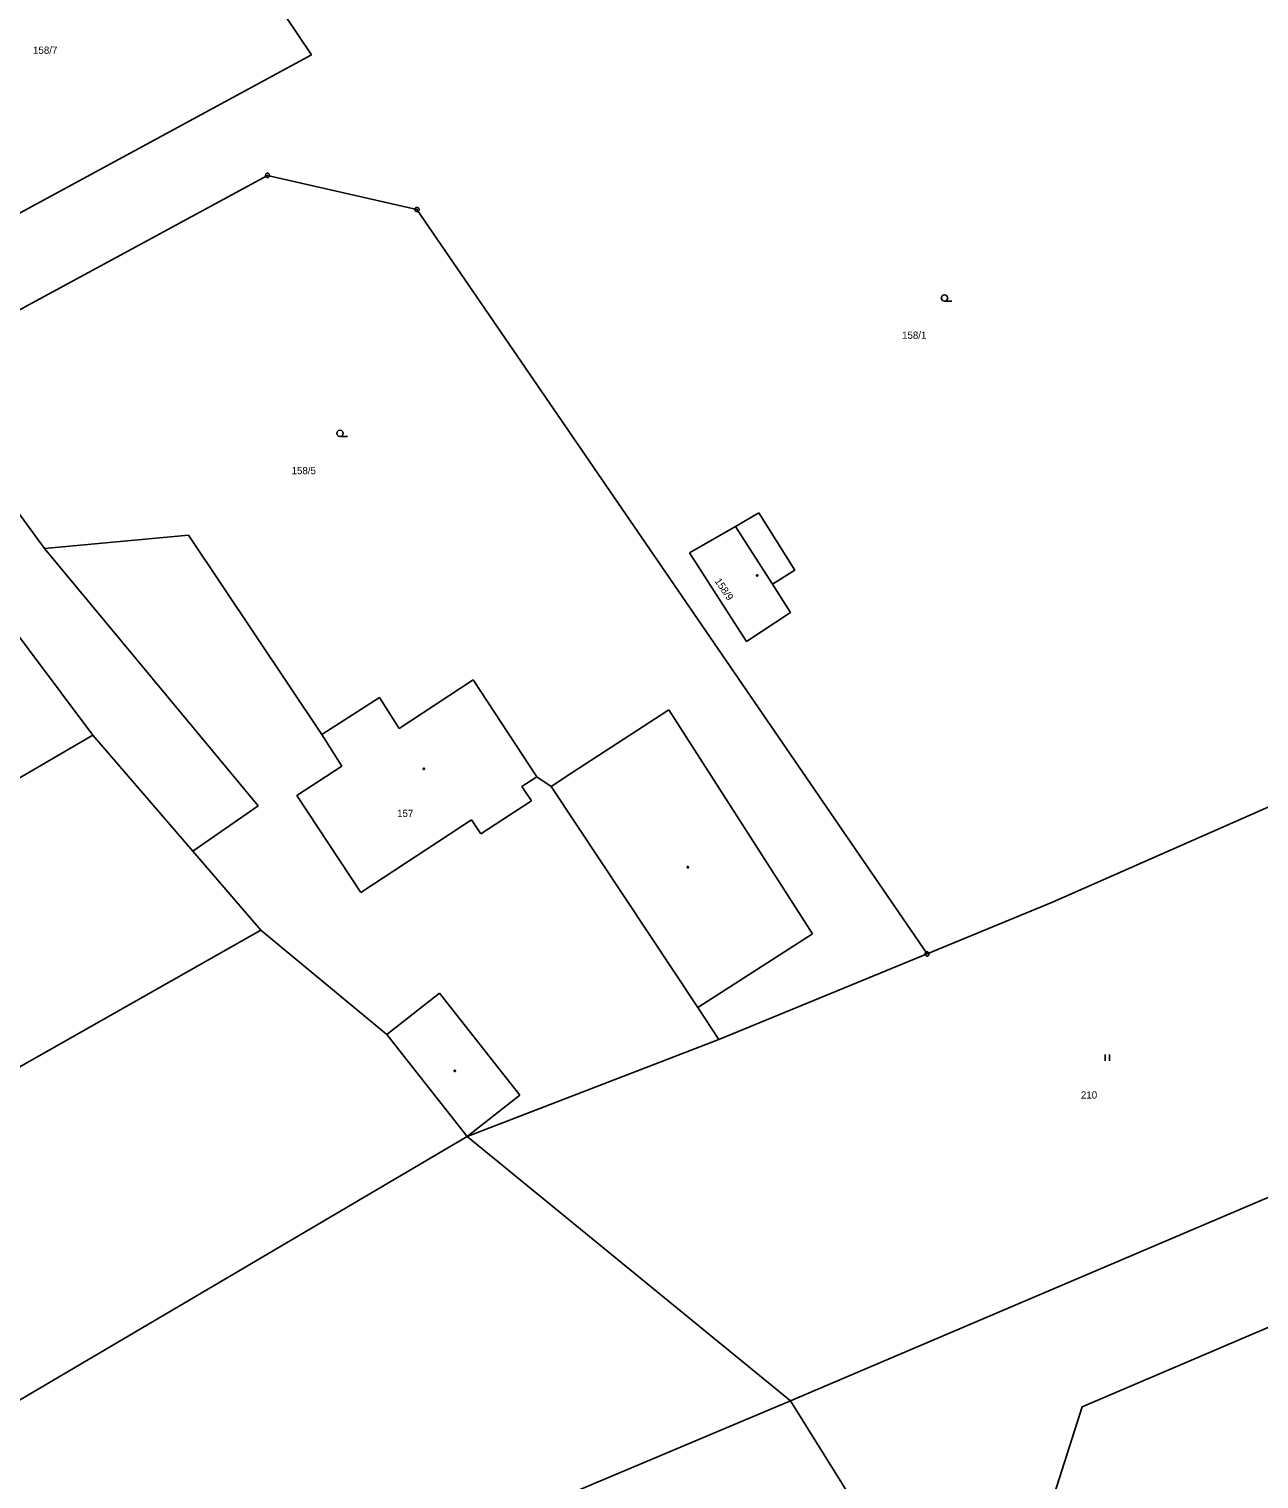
# Model space of a CAD drawing. Extents: x -871430 to -870620, y -1010094 to -1009649.
# Drawn here: x -870895.2 to -870823.3, y -1009941.8 to -1009857 of the extents above; entities that cross this region are included whole.
import ezdxf

# ---------------------------------------------------------------- set-up
doc = ezdxf.new("R2010")
doc.units = 0
for name, color, linetype in [('Vrstva 1', 7, 'Continuous'), ('Vrstva 2', 7, 'Continuous'), ('Vrstva 3', 7, 'Continuous'), ('Vrstva 4', 7, 'Continuous'), ('Vrstva 5', 7, 'Continuous'), ('Vrstva 8', 7, 'Continuous')]:
    doc.layers.add(name, color=color, linetype=linetype)

msp = doc.modelspace()

# ---------------------------------------------------------------- linework, layer by layer
at = {"layer": 'Vrstva 1'}
for p, q in [((-870878.69, -1009858.54), (-870885.13, -1009848.9)), ((-870878.69, -1009858.54), (-870899.31, -1009869.72)), ((-870902.04, -1009876.85), (-870881.26, -1009865.58)), ((-870881.26, -1009865.58), (-870872.52, -1009867.58)), ((-870872.52, -1009867.58), (-870842.69, -1009911.12)), ((-870902.04, -1009876.85), (-870894.31, -1009887.4)), ((-870853.89, -1009886.11), (-870852.53, -1009885.32)), ((-870852.53, -1009885.32), (-870850.42, -1009888.67)), ((-870856.59, -1009887.66), (-870853.89, -1009886.11)), ((-870891.48, -1009898.32), (-870899.84, -1009887.16)), ((-870894.31, -1009887.4), (-870885.88, -1009886.62)), ((-870885.88, -1009886.62), (-870878.09, -1009898.28)), ((-870881.8, -1009902.45), (-870894.31, -1009887.4)), ((-870853.25, -1009892.85), (-870856.59, -1009887.66)), ((-870850.42, -1009888.67), (-870851.73, -1009889.5)), ((-870851.73, -1009889.5), (-870850.68, -1009891.15)), ((-870850.68, -1009891.15), (-870853.25, -1009892.85)), ((-870835.36, -1009908.1), (-870803.69, -1009894.13)), ((-870873.56, -1009897.93), (-870869.24, -1009895.09)), ((-870865.51, -1009900.76), (-870869.24, -1009895.09)), ((-870878.09, -1009898.28), (-870874.71, -1009896.12)), ((-870873.56, -1009897.93), (-870874.71, -1009896.12)), ((-870863.46, -1009900.53), (-870857.8, -1009896.85)), ((-870857.8, -1009896.85), (-870849.39, -1009909.94)), ((-870937.35, -1009925.05), (-870891.48, -1009898.32)), ((-870885.63, -1009905.11), (-870891.48, -1009898.32)), ((-870864.68, -1009901.32), (-870865.51, -1009900.76)), ((-870864.68, -1009901.32), (-870863.46, -1009900.53)), ((-870885.63, -1009905.11), (-870881.8, -1009902.45)), ((-870881.66, -1009909.72), (-870885.63, -1009905.11)), ((-870842.69, -1009911.12), (-870835.36, -1009908.1)), ((-870935.49, -1009940.26), (-870881.66, -1009909.72)), ((-870874.28, -1009915.83), (-870881.66, -1009909.72)), ((-870856.1, -1009914.25), (-870849.39, -1009909.94)), ((-870842.69, -1009911.12), (-870854.86, -1009916.13)), ((-870854.86, -1009916.13), (-870856.1, -1009914.25)), ((-870850.67, -1009937.26), (-870796.84, -1009914.3)), ((-870869.59, -1009921.79), (-870874.28, -1009915.83)), ((-870854.86, -1009916.13), (-870869.59, -1009921.79)), ((-870924.06, -1009953.89), (-870869.59, -1009921.79)), ((-870850.67, -1009937.26), (-870869.59, -1009921.79)), ((-870850.67, -1009937.26), (-870890.37, -1009953.94)), ((-870837.15, -1009958.98), (-870850.67, -1009937.26))]:
    msp.add_line(p, q, dxfattribs=at)
msp.add_lwpolyline([(-870830.66, -1009955.85), (-870836.43, -1009946.41), (-870833.62, -1009937.6), (-870794.48, -1009920.9)], dxfattribs=at)
at = {"layer": 'Vrstva 3'}
for p, q in [((-870832.265, -1009917.005), (-870832.265, -1009917.38)), ((-870832.015, -1009917.38), (-870832.015, -1009917.005))]:
    msp.add_line(p, q, dxfattribs=at)
for points in [[(-870841.67, -1009872.94), (-870841.765, -1009872.915), (-870841.832, -1009872.845), (-870841.858, -1009872.752), (-870841.832, -1009872.66), (-870841.765, -1009872.59), (-870841.67, -1009872.565), (-870841.575, -1009872.59), (-870841.508, -1009872.66), (-870841.482, -1009872.752), (-870841.508, -1009872.845), (-870841.575, -1009872.915), (-870841.67, -1009872.94), (-870841.232, -1009872.94)], [(-870877.02, -1009880.86), (-870877.115, -1009880.835), (-870877.182, -1009880.765), (-870877.208, -1009880.672), (-870877.182, -1009880.58), (-870877.115, -1009880.51), (-870877.02, -1009880.485), (-870876.925, -1009880.51), (-870876.858, -1009880.58), (-870876.832, -1009880.672), (-870876.858, -1009880.765), (-870876.925, -1009880.835), (-870877.02, -1009880.86), (-870876.582, -1009880.86)]]:
    msp.add_lwpolyline(points, dxfattribs=at)
at = {"layer": 'Vrstva 4'}
for p, q in [((-870851.73, -1009889.5), (-870853.89, -1009886.11)), ((-870876.91, -1009900.13), (-870878.09, -1009898.28)), ((-870879.54, -1009901.86), (-870876.91, -1009900.13)), ((-870865.51, -1009900.76), (-870866.38, -1009901.33)), ((-870865.83, -1009902.16), (-870866.38, -1009901.33)), ((-870864.68, -1009901.32), (-870856.1, -1009914.25)), ((-870875.81, -1009907.53), (-870879.54, -1009901.86)), ((-870865.83, -1009902.16), (-870868.79, -1009904.1)), ((-870869.33, -1009903.27), (-870875.81, -1009907.53)), ((-870868.79, -1009904.1), (-870869.33, -1009903.27)), ((-870871.2, -1009913.41), (-870874.28, -1009915.83)), ((-870871.2, -1009913.41), (-870866.51, -1009919.37)), ((-870869.59, -1009921.79), (-870866.51, -1009919.37))]:
    msp.add_line(p, q, dxfattribs=at)
at = {"layer": 'Vrstva 5'}
for points in [[(-870852.62, -1009888.938), (-870852.595, -1009888.942), (-870852.582, -1009888.965), (-870852.578, -1009888.98), (-870852.582, -1009889.002), (-870852.602, -1009889.02), (-870852.62, -1009889.022), (-870852.642, -1009889.015), (-870852.658, -1009889), (-870852.662, -1009888.98), (-870852.658, -1009888.958), (-870852.638, -1009888.94), (-870852.62, -1009888.938)], [(-870872.12, -1009900.248), (-870872.095, -1009900.253), (-870872.082, -1009900.275), (-870872.078, -1009900.29), (-870872.082, -1009900.312), (-870872.102, -1009900.33), (-870872.12, -1009900.332), (-870872.142, -1009900.325), (-870872.158, -1009900.31), (-870872.162, -1009900.29), (-870872.158, -1009900.268), (-870872.138, -1009900.25), (-870872.12, -1009900.248)], [(-870856.658, -1009906.003), (-870856.635, -1009906.04), (-870856.658, -1009906.078), (-870856.702, -1009906.078), (-870856.725, -1009906.04), (-870856.702, -1009906.003), (-870856.658, -1009906.003)], [(-870870.288, -1009917.922), (-870870.265, -1009917.96), (-870870.288, -1009917.997), (-870870.332, -1009917.997), (-870870.355, -1009917.96), (-870870.332, -1009917.922), (-870870.288, -1009917.922)]]:
    msp.add_lwpolyline(points, dxfattribs=at)
at = {"layer": 'Vrstva 8'}
for p, q in [((-870881.272, -1009865.58), (-870881.248, -1009865.58)), ((-870872.532, -1009867.58), (-870872.508, -1009867.58)), ((-870842.702, -1009911.12), (-870842.678, -1009911.12))]:
    msp.add_line(p, q, dxfattribs=at)
for points in [[(-870881.222, -1009865.46), (-870881.16, -1009865.508), (-870881.135, -1009865.58), (-870881.16, -1009865.652), (-870881.222, -1009865.7), (-870881.298, -1009865.7), (-870881.36, -1009865.652), (-870881.385, -1009865.58), (-870881.36, -1009865.508), (-870881.298, -1009865.46), (-870881.222, -1009865.46)], [(-870872.482, -1009867.46), (-870872.42, -1009867.508), (-870872.395, -1009867.58), (-870872.42, -1009867.652), (-870872.482, -1009867.7), (-870872.558, -1009867.7), (-870872.62, -1009867.652), (-870872.645, -1009867.58), (-870872.62, -1009867.508), (-870872.558, -1009867.46), (-870872.482, -1009867.46)], [(-870842.652, -1009911), (-870842.59, -1009911.048), (-870842.565, -1009911.12), (-870842.59, -1009911.192), (-870842.652, -1009911.24), (-870842.727, -1009911.24), (-870842.79, -1009911.192), (-870842.815, -1009911.12), (-870842.79, -1009911.048), (-870842.727, -1009911), (-870842.652, -1009911)]]:
    msp.add_lwpolyline(points, dxfattribs=at)

# ---------------------------------------------------------------- texts
at = {"layer": 'Vrstva 2'}
for s, p in [('158/7', (-870894.972, -1009858.47)), ('158/1', (-870844.152, -1009875.14)), ('158/5', (-870879.852, -1009883.06)), ('157', (-870873.682, -1009903.11)), ('210', (-870833.691, -1009919.58))]:
    msp.add_text(s, height=0.425, dxfattribs=at).set_placement(p)
msp.add_text('158/9', height=0.425, rotation=304.35518, dxfattribs=at).set_placement((-870855.134, -1009889.318))

doc.saveas('drawing.dxf')
